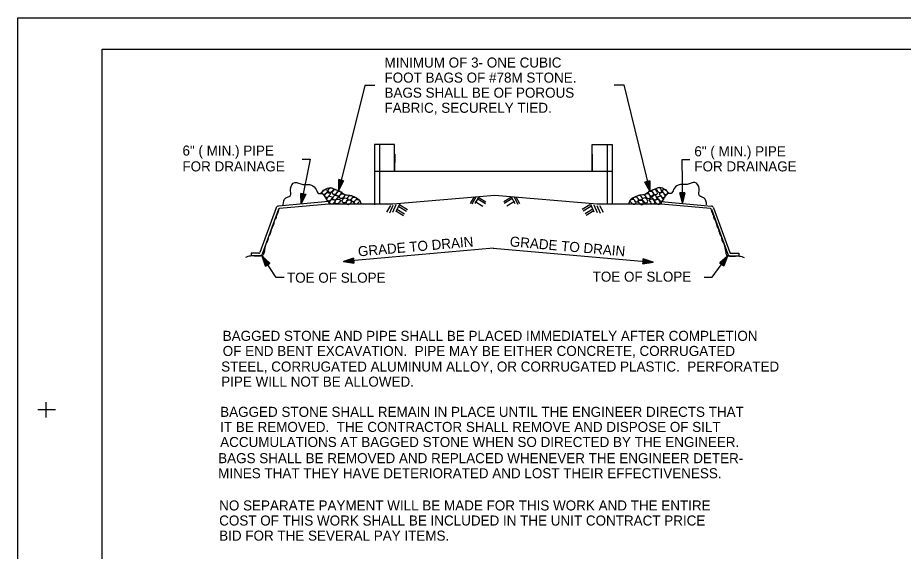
# Model space of a CAD drawing. Extents: x -41 to 191, y -168 to 6.
# Drawn here: x 0 to 25.32, y -133.35 to -118.09 of the extents above; entities that cross this region are included whole.
import ezdxf

# ---------------------------------------------------------------- set-up
doc = ezdxf.new("R2010")
doc.units = 0
for name, color, linetype in [('Arrowhead Terminators CELL', 7, 'Continuous'), ('Default', 7, 'Continuous'), ('Dimension Lines CELL', 7, 'Continuous'), ('Mis Object Lines', 7, 'Continuous'), ('Plan Sheet CELL', 7, 'Continuous'), ('Plot Shape CELL', 7, 'Continuous'), ('Text CELL', 7, 'Continuous'), ('User Information Notes CELL', 7, 'Continuous')]:
    doc.layers.add(name, color=color, linetype=linetype)

msp = doc.modelspace()

# ---------------------------------------------------------------- linework, layer by layer
at = {"layer": 'Arrowhead Terminators CELL'}
for points in [[(9.249, -122.739), (9.263, -122.743), (9.179, -123.018), (9.277, -122.747), (9.291, -122.75), (9.179, -123.018), (9.305, -122.754), (9.319, -122.757), (9.179, -123.018), (9.179, -122.722), (9.193, -122.726), (9.179, -123.018), (9.207, -122.729), (9.221, -122.733), (9.179, -123.018), (9.235, -122.736), (9.319, -122.757), (9.179, -122.722), (9.179, -123.018), (9.319, -122.757)], [(18.003, -122.776), (18.017, -122.772), (18.072, -123.055), (18.031, -122.769), (18.045, -122.765), (18.072, -123.055), (18.059, -122.762), (18.073, -122.759), (18.072, -123.055), (17.933, -122.793), (17.947, -122.789), (18.072, -123.055), (17.961, -122.786), (17.975, -122.783), (18.072, -123.055), (17.989, -122.779), (18.073, -122.759), (17.933, -122.793), (18.072, -123.055), (18.073, -122.759)], [(8.163, -123.129), (8.177, -123.132), (8.107, -123.411), (8.191, -123.135), (8.205, -123.138), (8.107, -123.411), (8.219, -123.14), (8.233, -123.143), (8.107, -123.411), (8.092, -123.115), (8.106, -123.118), (8.107, -123.411), (8.121, -123.121), (8.135, -123.124), (8.107, -123.411), (8.149, -123.126), (8.233, -123.143), (8.092, -123.115), (8.107, -123.411), (8.233, -123.143)], [(18.998, -123.103), (19.013, -123.103), (19.003, -123.39), (19.027, -123.102), (19.041, -123.102), (19.003, -123.39), (19.056, -123.102), (19.07, -123.102), (19.003, -123.39), (18.926, -123.104), (18.941, -123.104), (19.003, -123.39), (18.955, -123.104), (18.97, -123.103), (19.003, -123.39), (18.984, -123.103), (19.07, -123.102), (18.926, -123.104), (19.003, -123.39), (19.07, -123.102)], [(7.147, -125.154), (7.135, -125.162), (6.987, -124.915), (7.123, -125.169), (7.111, -125.177), (6.987, -124.915), (7.099, -125.186), (7.087, -125.194), (6.987, -124.915), (7.206, -125.113), (7.195, -125.121), (6.987, -124.915), (7.183, -125.129), (7.171, -125.137), (6.987, -124.915), (7.159, -125.146), (7.087, -125.194), (7.206, -125.113), (6.987, -124.915), (7.087, -125.194)], [(9.605, -125.034), (9.606, -125.048), (9.319, -125.059), (9.607, -125.063), (9.609, -125.077), (9.319, -125.059), (9.61, -125.091), (9.611, -125.106), (9.319, -125.059), (9.599, -124.963), (9.6, -124.977), (9.319, -125.059), (9.601, -124.991), (9.602, -125.006), (9.319, -125.059), (9.604, -125.02), (9.611, -125.106), (9.599, -124.963), (9.319, -125.059), (9.611, -125.106)], [(17.88, -125.059), (17.881, -125.045), (18.166, -125.084), (17.882, -125.03), (17.883, -125.016), (18.166, -125.084), (17.885, -125.002), (17.886, -124.987), (18.166, -125.084), (17.873, -125.131), (17.875, -125.116), (18.166, -125.084), (17.876, -125.102), (17.877, -125.088), (18.166, -125.084), (17.878, -125.073), (17.886, -124.987), (17.873, -125.131), (18.166, -125.084), (17.886, -124.987)], [(20.127, -125.141), (20.115, -125.132), (20.297, -124.909), (20.104, -125.124), (20.092, -125.115), (20.297, -124.909), (20.08, -125.107), (20.069, -125.098), (20.297, -124.909), (20.185, -125.183), (20.173, -125.175), (20.297, -124.909), (20.161, -125.166), (20.15, -125.158), (20.297, -124.909), (20.138, -125.149), (20.069, -125.098), (20.185, -125.183), (20.297, -124.909), (20.069, -125.098)]]:
    msp.add_lwpolyline(points, dxfattribs=at)
at = {"layer": 'Default'}
for p, q in [((10.346, -121.716), (10.203, -121.716)), ((10.203, -121.716), (10.203, -123.439)), ((10.777, -121.716), (10.346, -121.716)), ((10.346, -121.716), (10.346, -122.933)), ((10.777, -122.481), (10.777, -121.716)), ((16.425, -122.481), (16.425, -121.716)), ((16.425, -121.716), (16.856, -121.716)), ((16.856, -121.716), (16.856, -122.933)), ((16.856, -121.716), (17, -121.716)), ((17, -121.716), (17, -123.419)), ((10.782, -121.996), (10.777, -122.481)), ((16.421, -121.996), (16.425, -122.481)), ((10.346, -122.933), (10.346, -123.424)), ((16.856, -122.933), (16.856, -123.424)), ((7.392, -123.524), (6.927, -124.803)), ((8.885, -123.351), (7.454, -123.477)), ((8.885, -123.351), (8.891, -123.423)), ((18.4, -123.351), (18.393, -123.423)), ((18.4, -123.351), (19.831, -123.477)), ((19.892, -123.524), (20.358, -124.803)), ((7.452, -123.57), (6.986, -124.851)), ((19.833, -123.57), (20.299, -124.851)), ((6.893, -124.826), (6.671, -124.826)), ((6.671, -124.826), (6.671, -124.898)), ((6.918, -124.898), (6.671, -124.898)), ((20.367, -124.898), (20.613, -124.898)), ((20.392, -124.826), (20.613, -124.826)), ((20.613, -124.826), (20.613, -124.898))]:
    msp.add_line(p, q, dxfattribs=at)
msp.add_lwpolyline([(7.486, -123.541), (8.894, -123.418), (10.722, -123.418), (13.644, -123.162), (16.569, -123.418), (18.396, -123.418), (19.805, -123.541)], dxfattribs=at)
for centre, radius, start, end in [((7.46, -123.548), 0.0718, 94.9999, 159.9996), ((7.486, -123.582), 0.0359, 95, 160), ((19.799, -123.582), 0.0359, 20, 85), ((19.825, -123.548), 0.0718, 20.0004, 85.0001), ((6.893, -124.791), 0.0359, 270, 339.9994), ((20.392, -124.791), 0.0359, 200.0006, 270), ((6.918, -124.827), 0.0718, 270, 340), ((20.367, -124.827), 0.0718, 200, 270)]:
    msp.add_arc(centre, radius, start, end, dxfattribs=at)
for points in [[(7.588, -123.445), (7.667, -123.244), (7.789, -123.189), (7.801, -122.982), (7.923, -122.805), (8.149, -122.86), (8.277, -122.86), (8.399, -122.878), (8.533, -123.006), (8.606, -123.116), (8.71, -123.128), (8.789, -123.226), (8.875, -123.348)], [(19.697, -123.445), (19.618, -123.244), (19.496, -123.189), (19.483, -122.982), (19.362, -122.805), (19.136, -122.86), (19.008, -122.86), (18.886, -122.878), (18.752, -123.006), (18.678, -123.116), (18.575, -123.128), (18.495, -123.226), (18.41, -123.348)], [(8.673, -123.11), (8.783, -123.006), (8.929, -122.951), (9.113, -123.012), (9.222, -123.061), (9.338, -123.14), (9.497, -123.171), (9.649, -123.226), (9.783, -123.323), (9.82, -123.421)], [(8.698, -123.104), (8.759, -123.012), (8.814, -123.012), (8.868, -123.049), (8.85, -123.073), (8.814, -123.116), (8.771, -123.146), (8.71, -123.128), (8.698, -123.11)], [(8.868, -123.049), (8.929, -122.957), (8.984, -122.957), (9.039, -122.994), (9.021, -123.018), (8.984, -123.061), (8.942, -123.092), (8.881, -123.073), (8.868, -123.055)], [(8.99, -123.104), (9.051, -123.012), (9.106, -123.012), (9.161, -123.049), (9.143, -123.073), (9.106, -123.116), (9.064, -123.146), (9.003, -123.128), (8.99, -123.11)], [(18.611, -123.11), (18.502, -123.006), (18.355, -122.951), (18.172, -123.012), (18.062, -123.061), (17.947, -123.14), (17.788, -123.171), (17.636, -123.226), (17.501, -123.323), (17.465, -123.421)], [(18.294, -123.104), (18.233, -123.012), (18.178, -123.012), (18.123, -123.049), (18.142, -123.073), (18.178, -123.116), (18.221, -123.146), (18.282, -123.128), (18.294, -123.11)], [(18.416, -123.049), (18.355, -122.957), (18.3, -122.957), (18.245, -122.994), (18.264, -123.018), (18.3, -123.061), (18.343, -123.092), (18.404, -123.073), (18.416, -123.055)], [(18.587, -123.104), (18.526, -123.012), (18.471, -123.012), (18.416, -123.049), (18.434, -123.073), (18.471, -123.116), (18.514, -123.146), (18.575, -123.128), (18.587, -123.11)], [(8.771, -123.189), (8.832, -123.098), (8.887, -123.098), (8.942, -123.134), (8.923, -123.159), (8.887, -123.201), (8.844, -123.232), (8.783, -123.214), (8.771, -123.195)], [(8.832, -123.293), (8.893, -123.201), (8.948, -123.201), (9.003, -123.238), (8.984, -123.262), (8.948, -123.305), (8.905, -123.335), (8.844, -123.317), (8.832, -123.299)], [(8.911, -123.384), (8.972, -123.293), (9.027, -123.293), (9.082, -123.329), (9.064, -123.354), (9.027, -123.396), (8.984, -123.427), (8.923, -123.409), (8.911, -123.39)], [(9.003, -123.262), (9.064, -123.171), (9.118, -123.171), (9.173, -123.207), (9.155, -123.232), (9.118, -123.274), (9.076, -123.305), (9.015, -123.287), (9.003, -123.268)], [(9.064, -123.372), (9.125, -123.281), (9.179, -123.281), (9.234, -123.317), (9.216, -123.342), (9.179, -123.384), (9.137, -123.415), (9.076, -123.396), (9.064, -123.378)], [(9.094, -123.153), (9.155, -123.061), (9.21, -123.061), (9.265, -123.098), (9.247, -123.122), (9.21, -123.165), (9.167, -123.195), (9.106, -123.177), (9.094, -123.159)], [(9.192, -123.22), (9.253, -123.128), (9.308, -123.128), (9.363, -123.165), (9.344, -123.189), (9.308, -123.232), (9.265, -123.262), (9.204, -123.244), (9.192, -123.226)], [(9.271, -123.342), (9.332, -123.25), (9.387, -123.25), (9.442, -123.287), (9.423, -123.311), (9.387, -123.354), (9.344, -123.384), (9.283, -123.366), (9.271, -123.348)], [(9.387, -123.396), (9.448, -123.305), (9.503, -123.305), (9.558, -123.342), (9.539, -123.366), (9.503, -123.409), (9.46, -123.439), (9.399, -123.421), (9.387, -123.403)], [(9.423, -123.268), (9.484, -123.177), (9.539, -123.177), (9.594, -123.214), (9.576, -123.238), (9.539, -123.281), (9.497, -123.311), (9.436, -123.293), (9.423, -123.274)], [(9.521, -123.317), (9.582, -123.226), (9.637, -123.226), (9.692, -123.262), (9.673, -123.287), (9.637, -123.329), (9.594, -123.36), (9.533, -123.342), (9.521, -123.323)], [(9.613, -123.384), (9.673, -123.293), (9.728, -123.293), (9.783, -123.329), (9.765, -123.354), (9.728, -123.396), (9.686, -123.427), (9.625, -123.409), (9.613, -123.39)], [(17.672, -123.384), (17.611, -123.293), (17.556, -123.293), (17.501, -123.329), (17.52, -123.354), (17.556, -123.396), (17.599, -123.427), (17.66, -123.409), (17.672, -123.39)], [(17.764, -123.317), (17.703, -123.226), (17.648, -123.226), (17.593, -123.262), (17.611, -123.287), (17.648, -123.329), (17.69, -123.36), (17.751, -123.342), (17.764, -123.323)], [(17.861, -123.268), (17.8, -123.177), (17.745, -123.177), (17.69, -123.214), (17.709, -123.238), (17.745, -123.281), (17.788, -123.311), (17.849, -123.293), (17.861, -123.274)], [(17.898, -123.396), (17.837, -123.305), (17.782, -123.305), (17.727, -123.342), (17.745, -123.366), (17.782, -123.409), (17.825, -123.439), (17.886, -123.421), (17.898, -123.403)], [(18.014, -123.342), (17.953, -123.25), (17.898, -123.25), (17.843, -123.287), (17.861, -123.311), (17.898, -123.354), (17.94, -123.384), (18.002, -123.366), (18.014, -123.348)], [(18.093, -123.22), (18.032, -123.128), (17.977, -123.128), (17.922, -123.165), (17.94, -123.189), (17.977, -123.232), (18.02, -123.262), (18.081, -123.244), (18.093, -123.226)], [(18.191, -123.153), (18.129, -123.061), (18.075, -123.061), (18.02, -123.098), (18.038, -123.122), (18.075, -123.165), (18.117, -123.195), (18.178, -123.177), (18.191, -123.159)], [(18.221, -123.372), (18.16, -123.281), (18.105, -123.281), (18.05, -123.317), (18.069, -123.342), (18.105, -123.384), (18.148, -123.415), (18.209, -123.396), (18.221, -123.378)], [(18.282, -123.262), (18.221, -123.171), (18.166, -123.171), (18.111, -123.207), (18.129, -123.232), (18.166, -123.274), (18.209, -123.305), (18.27, -123.287), (18.282, -123.268)], [(18.373, -123.384), (18.313, -123.293), (18.258, -123.293), (18.203, -123.329), (18.221, -123.354), (18.258, -123.396), (18.3, -123.427), (18.361, -123.409), (18.373, -123.39)], [(18.453, -123.293), (18.392, -123.201), (18.337, -123.201), (18.282, -123.238), (18.3, -123.262), (18.337, -123.305), (18.38, -123.335), (18.441, -123.317), (18.453, -123.299)], [(18.514, -123.189), (18.453, -123.098), (18.398, -123.098), (18.343, -123.134), (18.361, -123.159), (18.398, -123.201), (18.441, -123.232), (18.502, -123.214), (18.514, -123.195)], [(7.466, -123.561), (7.444, -123.634), (7.417, -123.711), (7.396, -123.753), (7.38, -123.836), (7.35, -123.875), (7.31, -124.016), (7.246, -124.156), (7.204, -124.299), (7.167, -124.36), (7.161, -124.418), (7.097, -124.558), (7.06, -124.717), (6.987, -124.897), (6.874, -124.906), (6.804, -124.909), (6.725, -124.903), (6.658, -124.906), (6.578, -124.924), (6.511, -124.949)], [(19.819, -123.561), (19.84, -123.634), (19.868, -123.711), (19.889, -123.753), (19.904, -123.836), (19.935, -123.875), (19.974, -124.016), (20.038, -124.156), (20.081, -124.299), (20.118, -124.36), (20.124, -124.418), (20.188, -124.558), (20.224, -124.717), (20.298, -124.897), (20.411, -124.906), (20.481, -124.909), (20.56, -124.903), (20.627, -124.906), (20.706, -124.924), (20.773, -124.949)]]:
    msp.add_spline(points, degree=3, dxfattribs=at)
at = {"layer": 'Dimension Lines CELL'}
for p, q in [((9.925, -120.035), (9.179, -123.018)), ((10.214, -120.035), (9.925, -120.035)), ((17.052, -120.016), (17.327, -120.016)), ((17.327, -120.016), (18.072, -123.055)), ((8.362, -122.134), (8.107, -123.411)), ((8.132, -122.134), (8.362, -122.134)), ((19.214, -122.16), (18.984, -122.16)), ((18.984, -122.16), (19.003, -123.39)), ((13.046, -123.214), (12.936, -123.409)), ((13.095, -123.226), (12.985, -123.421)), ((13.18, -123.214), (13.071, -123.409)), ((13.156, -123.274), (13.376, -123.409)), ((13.168, -123.226), (13.388, -123.36)), ((14.116, -123.226), (13.897, -123.36)), ((14.129, -123.274), (13.909, -123.409)), ((14.104, -123.214), (14.214, -123.409)), ((14.19, -123.226), (14.299, -123.421)), ((14.239, -123.214), (14.348, -123.409)), ((10.655, -123.458), (10.546, -123.653)), ((10.729, -123.458), (10.631, -123.677)), ((10.814, -123.445), (10.716, -123.665)), ((10.912, -123.421), (10.814, -123.64)), ((10.899, -123.494), (11.119, -123.628)), ((10.924, -123.445), (11.143, -123.579)), ((13.083, -123.348), (13.302, -123.482)), ((14.202, -123.348), (13.982, -123.482)), ((16.361, -123.445), (16.141, -123.579)), ((16.385, -123.494), (16.166, -123.628)), ((16.373, -123.421), (16.471, -123.64)), ((16.471, -123.445), (16.568, -123.665)), ((16.556, -123.458), (16.654, -123.677)), ((16.629, -123.458), (16.739, -123.653)), ((10.814, -123.616), (11.033, -123.75)), ((10.838, -123.567), (11.058, -123.701)), ((16.446, -123.567), (16.227, -123.701)), ((16.471, -123.616), (16.251, -123.75)), ((13.607, -124.684), (9.319, -125.059)), ((13.594, -124.684), (18.166, -125.084)), ((7.392, -125.519), (6.987, -124.915)), ((19.859, -125.507), (20.297, -124.909)), ((7.622, -125.519), (7.392, -125.519)), ((19.629, -125.507), (19.859, -125.507))]:
    msp.add_line(p, q, dxfattribs=at)
at = {"layer": 'Mis Object Lines'}
msp.add_line((10.203, -122.481), (17, -122.481), dxfattribs=at)
at = {"layer": 'Plan Sheet CELL'}
for p, q in [((0, -118.093), (0, -118.093)), ((2.412, -118.994), (75.628, -118.994)), ((2.412, -167.042), (2.412, -118.994)), ((0.818, -129.52), (0.818, -129.086)), ((0.573, -129.29), (1.076, -129.29))]:
    msp.add_line(p, q, dxfattribs=at)
at = {"layer": 'Plot Shape CELL'}
msp.add_lwpolyline([(0, -118.093), (75.648, -118.093), (75.648, -168.429), (0, -168.429)], close=True, dxfattribs=at)
at = {"layer": 'User Information Notes CELL'}
msp.add_line((2.412, -118.994), (2.412, -118.994), dxfattribs=at)

# ---------------------------------------------------------------- texts
at = {"layer": 'Text CELL'}
for s, height, p in [('MINIMUM OF 3- ONE CUBIC', 0.28738, (10.486, -119.518)), ('FOOT BAGS OF #78M STONE.', 0.2874, (10.486, -119.949)), ('BAGS SHALL BE OF POROUS', 0.28739, (10.486, -120.38)), ('FABRIC, SECURELY TIED.', 0.28738, (10.486, -120.812)), ('6" ( MIN.) PIPE', 0.2874, (4.711, -122.035)), ('6" ( MIN.) PIPE', 0.28738, (19.345, -122.056)), ('FOR DRAINAGE', 0.28739, (4.71, -122.487)), ('FOR DRAINAGE', 0.28739, (19.345, -122.487)), ('TOE OF SLOPE', 0.28738, (7.698, -125.67)), ('TOE OF SLOPE', 0.28738, (16.437, -125.64)), ('BAGGED STONE AND PIPE SHALL BE PLACED IMMEDIATELY AFTER COMPLETION', 0.28739, (5.861, -127.332)), ('OF END BENT EXCAVATION.  PIPE MAY BE EITHER CONCRETE, CORRUGATED', 0.28739, (5.861, -127.764)), ('STEEL, CORRUGATED ALUMINUM ALLOY, OR CORRUGATED PLASTIC.  PERFORATED', 0.2874, (5.818, -128.21)), ('PIPE WILL NOT BE ALLOWED.', 0.28739, (5.818, -128.641)), ('BAGGED STONE SHALL REMAIN IN PLACE UNTIL THE ENGINEER DIRECTS THAT', 0.2874, (5.789, -129.505)), ('IT BE REMOVED.  THE CONTRACTOR SHALL REMOVE AND DISPOSE OF SILT', 0.28739, (5.789, -129.936)), ('ACCUMULATIONS AT BAGGED STONE WHEN SO DIRECTED BY THE ENGINEER.', 0.28738, (5.789, -130.367)), ('BAGS SHALL BE REMOVED AND REPLACED WHENEVER THE ENGINEER DETER-', 0.2874, (5.731, -130.829)), ('MINES THAT THEY HAVE DETERIORATED AND LOST THEIR EFFECTIVENESS.', 0.28739, (5.731, -131.26)), ('NO SEPARATE PAYMENT WILL BE MADE FOR THIS WORK AND THE ENTIRE', 0.28739, (5.76, -132.181)), ('COST OF THIS WORK SHALL BE INCLUDED IN THE UNIT CONTRACT PRICE', 0.28738, (5.76, -132.612)), ('BID FOR THE SEVERAL PAY ITEMS.', 0.28738, (5.76, -133.044))]:
    msp.add_text(s, height=height, dxfattribs=at).set_placement(p)
for height, rotation, p in [(0.28739, 4.9997, (9.74, -124.92)), (0.2874, 355, (14.059, -124.629))]:
    msp.add_text('GRADE TO DRAIN', height=height, rotation=rotation, dxfattribs=at).set_placement(p)

doc.saveas('drawing.dxf')
